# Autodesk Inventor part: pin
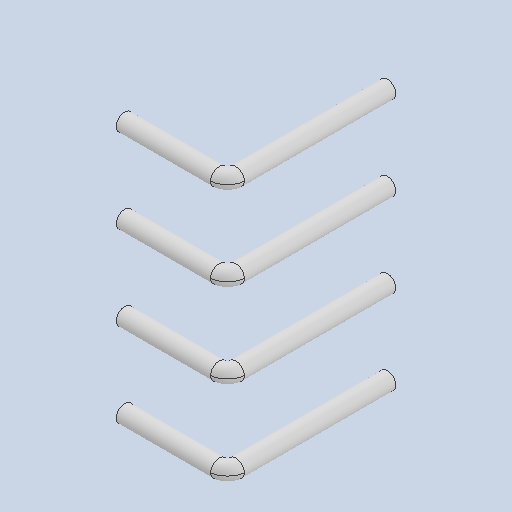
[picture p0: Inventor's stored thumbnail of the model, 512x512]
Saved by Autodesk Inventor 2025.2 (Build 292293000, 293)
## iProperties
Created: 2025-04
Part Number: pin
Material: Generic
Description: PART--DESC
Document SubType Name: Modeling
Designer: BennF
Density: 1 g/cm^3
Appearance: Default
Author: BennF
Revision Number: NONE
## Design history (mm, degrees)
feature "Solid"
feature "Solid:1"
feature "Solid:2"
feature "Solid:3"
body "Solid1"
body "Solid2"
body "Solid3"
body "Solid4"
